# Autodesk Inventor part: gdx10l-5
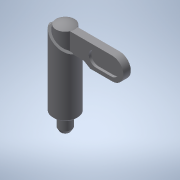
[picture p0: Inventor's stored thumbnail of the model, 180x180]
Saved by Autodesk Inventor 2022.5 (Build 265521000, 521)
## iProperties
Created: 2016-12
Part Number: gdx10l-5
Material: 一般
Document SubType Name: Modeling
Designer: imaocorp
Density: 1 g/cm^3
Appearance: 既定
Author: imaocorp
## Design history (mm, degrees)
node "gdx10l-5.x_t1"
node "gdx10l-5"
node "Base1"
